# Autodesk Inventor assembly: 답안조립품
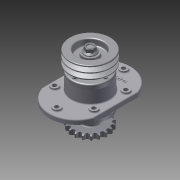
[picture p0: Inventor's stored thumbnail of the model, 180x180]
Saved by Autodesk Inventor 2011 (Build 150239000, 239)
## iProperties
Created: 2015-02
Part Number: 답안조립품
Document SubType Name: Assembly
Designer: Administrator
Author: Administrator
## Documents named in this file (11)
- C:\Documents and Settings\Administrator\바탕 화면\450207V1010\답안조립품.iam
- C:\Documents and Settings\Administrator\바탕 화면\450207V1010\본체.ipt
- C:\Documents and Settings\Administrator\바탕 화면\450207V1010\2-커버.ipt
- C:\Documents and Settings\Administrator\바탕 화면\450207V1010\3-축.ipt
- C:\Documents and Settings\Administrator\바탕 화면\450207V1010\11-키 6x6.ipt
- C:\Documents and Settings\Administrator\바탕 화면\450207V1010\4-V벨트풀리.ipt
- C:\Documents and Settings\Administrator\바탕 화면\450207V1010\9-M16-너트.ipt
- C:\Documents and Settings\Administrator\바탕 화면\450207V1010\5-체인 스프로킷.ipt
- C:\Documents and Settings\Administrator\바탕 화면\450207V1010\6-베어링 6206.ipt
- C:\Documents and Settings\Administrator\바탕 화면\450207V1010\10-M6.ipt
- C:\Documents and Settings\Administrator\바탕 화면\450207V1010\8-오일실 30x42.ipt
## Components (21 placed, 9 different names)
1. 2-커버:1
2. 2-커버:2
3. 3-축:1
4. 11-키 6x6:1
5. 11-키 6x6:2 — 각도:2
6. 4-V벨트풀리:1
7. 9-M16 너트:1
8. 5-체인 스프로킷:1 — 각도:2
9. 9-M16 너트:2
10. 6-베어링 6206:1
11. 6-베어링 6206:2
12. 8-8-오일실 30x42:1
13. 8-8-오일실 30x42:2
14. 10-M6:1
15. 10-M6:3
16. 10-M6:4
17. 10-M6:5
18. 10-M6:2
19. 10-M6:6
20. 10-M6:7
21. 10-M6:8
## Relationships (1: Angle 1)
- 각도:2 [Angle]: 11-키 6x6:2 ↔ 5-체인 스프로킷:1
